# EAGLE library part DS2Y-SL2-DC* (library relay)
MINIATURE RELAY NAiS Source: http://www.mew-europe.com/.. en_ds_61005_0023.pdf
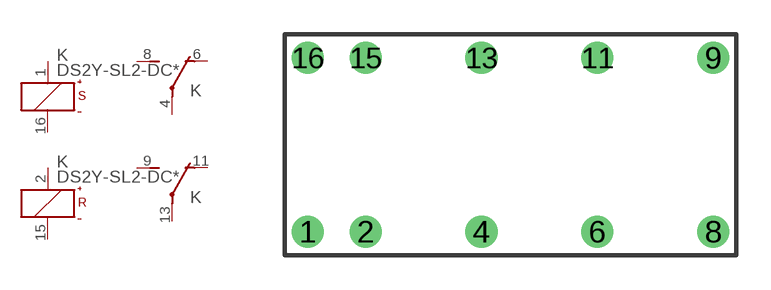
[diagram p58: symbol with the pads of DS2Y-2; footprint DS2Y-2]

Designator prefix K; gates 1=U 2=U S=K+-S R=K+-R

## DS2Y-SL2-DC1.5V (MPN: DS2Y-SL2-DC1.5V; OC_FARNELL: unknown; OC_NEWARK: 10C5841), DS2Y-SL2-DC3V (MPN: DS2Y-SL2-DC3V; OC_FARNELL: unknown; OC_NEWARK: 91B6712), DS2Y-SL2-DC5V (MF: AROMAT/ MATSUSHITA; MPN: DS2Y-SL2-DC5V; OC_FARNELL: unknown; OC_NEWARK: 93F4484), DS2Y-SL2-DC6V (MPN: DS2Y-SL2-DC6V; OC_FARNELL: unknown; OC_NEWARK: 99F8886), DS2Y-SL2-DC9V (MPN: DS2Y-SL2-DC9V; OC_FARNELL: unknown; OC_NEWARK: 10C5848), DS2Y-SL2-DC12V (MF: AROMAT/ MATSUSHITA; MPN: DS2Y-SL2-DC12V; OC_FARNELL: unknown; OC_NEWARK: 52F9208), DS2Y-SL2-DC24V (MPN: DS2Y-SL2-DC24V; OC_FARNELL: 1372981; OC_NEWARK: 64K3125), DS2Y-SL2-DC48V (MPN: DS2Y-SL2-DC48V; OC_FARNELL: unknown; OC_NEWARK: 10C5844)  [DS2Y-2]
1  S:+  pas
2  R:+  pas
4  1:P  pas
6  1:O  pas
8  1:S  pas
9  2:S  pas
11  2:O  pas
13  2:P  pas
15  R:-  pas
16  S:-  pas

## Footprint DS2Y-2 (pad centres in mm)
MINIATURE RELAY NAiS Source: http://www.mew-europe.com/.. en_ds_61005_0023.pdf
drill 0.9 round: 1 -8.89,-3.81; 2 -6.35,-3.81; 4 -1.27,-3.81; 6 3.81,-3.81; 8 8.89,-3.81; 9 8.89,3.81; 11 3.81,3.81; 13 -1.27,3.81; 15 -6.35,3.81; 16 -8.89,3.81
